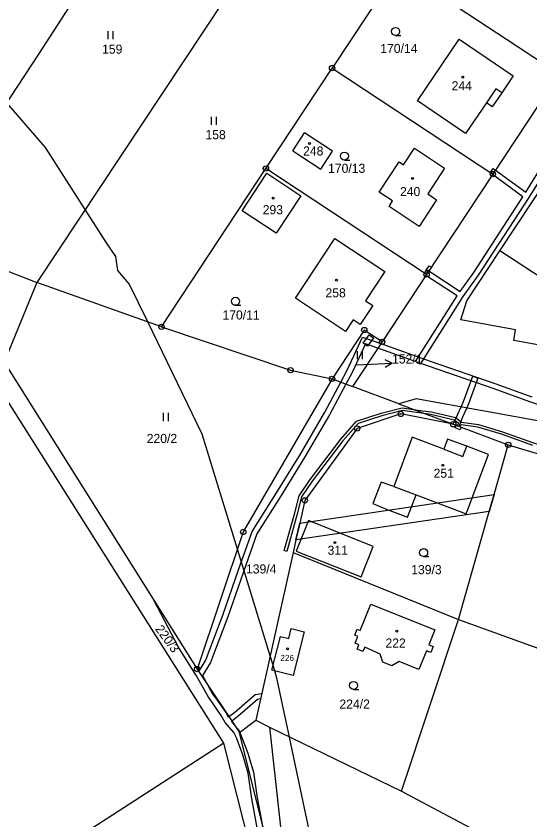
# Model space of a CAD drawing. Extents: x -747333 to -745433, y -1133152 to -1130600.
# Drawn here: x -746635.6 to -746539.4, y -1132011.9 to -1131861.6 of the extents above; entities that cross this region are included whole.
import ezdxf

# ---------------------------------------------------------------- set-up
doc = ezdxf.new("R2010")
doc.units = 0
for name, color, linetype in [('Vrstva 1', 7, 'Continuous'), ('Vrstva 16', 7, 'Continuous'), ('Vrstva 18', 7, 'Continuous'), ('Vrstva 19', 7, 'Continuous'), ('Vrstva 24', 7, 'Continuous'), ('Vrstva 25', 7, 'Continuous'), ('Vrstva 3', 7, 'Continuous'), ('Vrstva 30', 7, 'Continuous'), ('Vrstva 37', 7, 'Continuous'), ('Vrstva 4', 7, 'Continuous'), ('Vrstva 52', 7, 'Continuous'), ('Vrstva 6', 7, 'Continuous')]:
    doc.layers.add(name, color=color, linetype=linetype)

msp = doc.modelspace()

# ---------------------------------------------------------------- linework, layer by layer
at = {"layer": 'Vrstva 1'}
for p, q in [((-746560.48, -1131877.38), (-746552.65, -1131865.89)), ((-746552.65, -1131865.89), (-746542.56, -1131872.76)), ((-746542.56, -1131872.76), (-746544.71, -1131875.9)), ((-746544.71, -1131875.9), (-746546.5, -1131878.51)), ((-746551.46, -1131883.51), (-746560.48, -1131877.38)), ((-746547.57, -1131877.78), (-746551.46, -1131883.51)), ((-746546.5, -1131878.51), (-746547.57, -1131877.78)), ((-746583.8, -1131886.76), (-746581.61, -1131883.41)), ((-746576.33, -1131886.85), (-746581.61, -1131883.41)), ((-746583.8, -1131886.76), (-746578.54, -1131890.2)), ((-746578.54, -1131890.2), (-746576.33, -1131886.85)), ((-746545.06, -1131905.46), (-746534.04, -1131888.76)), ((-746593.25, -1131898.01), (-746588.67, -1131890.97)), ((-746588.67, -1131890.97), (-746582.27, -1131895.15)), ((-746582.27, -1131895.15), (-746586.87, -1131902.18)), ((-746586.87, -1131902.18), (-746593.25, -1131898.01)), ((-746551.21, -1131914.79), (-746545.06, -1131905.46)), ((-746509.16, -1131929.13), (-746545.06, -1131905.46)), ((-746552.36, -1131918.38), (-746551.21, -1131914.79)), ((-746542.1, -1131920.25), (-746552.36, -1131918.38)), ((-746542.46, -1131922.22), (-746542.1, -1131920.25)), ((-746512.94, -1131927.58), (-746542.46, -1131922.22)), ((-746563.94, -1131934.09), (-746572.59, -1131930.85)), ((-746560.7, -1131933.13), (-746563.94, -1131934.09)), ((-746563.94, -1131934.09), (-746559.67, -1131935.69)), ((-746483.07, -1131947.25), (-746560.7, -1131933.13)), ((-746561.44, -1131940.34), (-746564.91, -1131949.57)), ((-746555.51, -1131942.57), (-746561.44, -1131940.34)), ((-746554.83, -1131940.71), (-746555.51, -1131942.57)), ((-746551.26, -1131942.03), (-746554.83, -1131940.71)), ((-746547.16, -1131943.56), (-746551.26, -1131942.03)), ((-746551.34, -1131954.67), (-746547.16, -1131943.56)), ((-746567.28, -1131948.71), (-746568.84, -1131952.76)), ((-746564.91, -1131949.57), (-746567.28, -1131948.71)), ((-746562.32, -1131955.31), (-746560.74, -1131951.14)), ((-746560.74, -1131951.14), (-746551.34, -1131954.67)), ((-746568.84, -1131952.76), (-746566.43, -1131953.71)), ((-746566.43, -1131953.71), (-746562.32, -1131955.31)), ((-746580.87, -1131955.94), (-746583.14, -1131961.66)), ((-746568.74, -1131960.75), (-746580.87, -1131955.94)), ((-746571.01, -1131966.47), (-746568.74, -1131960.75)), ((-746583.14, -1131961.66), (-746571.01, -1131966.47))]:
    msp.add_line(p, q, dxfattribs=at)
for points in [[(-746564.05, -1131852.51), (-746543.81, -1131865.86)], [(-746566.41, -1131856.09), (-746576.43, -1131871.29)], [(-746543.81, -1131865.86), (-746533.99, -1131872.33)], [(-746588.82, -1131890.07), (-746576.43, -1131871.29)], [(-746576.43, -1131871.29), (-746546.37, -1131891.11)], [(-746537.79, -1131878.09), (-746546.37, -1131891.11)], [(-746563.09, -1131889.4), (-746561, -1131886.29)], [(-746561, -1131886.29), (-746555.4, -1131890.01)], [(-746567.62, -1131894.48), (-746563.91, -1131888.85)], [(-746563.91, -1131888.85), (-746563.09, -1131889.4)], [(-746608.35, -1131919.68), (-746588.82, -1131890.07)], [(-746558.76, -1131909.9), (-746588.82, -1131890.07)], [(-746555.4, -1131890.01), (-746558.54, -1131894.79)], [(-746546.37, -1131891.11), (-746558.76, -1131909.9)], [(-746565.11, -1131896.12), (-746567.62, -1131894.48)], [(-746558.54, -1131894.79), (-746556.89, -1131895.9)], [(-746565.79, -1131897.18), (-746565.11, -1131896.12)], [(-746556.89, -1131895.9), (-746560.17, -1131900.92)], [(-746560.17, -1131900.92), (-746565.79, -1131897.18)], [(-746653.72, -1131902.76), (-746631.67, -1131911.42)], [(-746583.31, -1131914.32), (-746575.9, -1131903.14), (-746566.54, -1131909.35), (-746570.17, -1131914.83), (-746568.83, -1131915.71), (-746571.18, -1131919.26), (-746572.49, -1131918.39), (-746573.92, -1131920.55), (-746583.31, -1131914.32)], [(-746558.76, -1131909.9), (-746567.07, -1131922.49)], [(-746631.67, -1131911.42), (-746637.77, -1131926.3)], [(-746608.35, -1131919.68), (-746631.67, -1131911.42)], [(-746608.35, -1131919.68), (-746584.22, -1131927.79)], [(-746570.41, -1131920.29), (-746576.43, -1131929.41)], [(-746567.07, -1131922.49), (-746570.41, -1131920.29)], [(-746637.77, -1131926.3), (-746601.69, -1131983.7)], [(-746584.22, -1131927.79), (-746576.43, -1131929.41)], [(-746576.43, -1131929.41), (-746593.05, -1131958.05)], [(-746576.43, -1131929.41), (-746572.59, -1131930.85)], [(-746596.68, -1131997.54), (-746638.63, -1131931.22)], [(-746559.67, -1131935.69), (-746553.77, -1131937.9)], [(-746563.57, -1131935.97), (-746571.75, -1131938.7)], [(-746553.77, -1131937.9), (-746563.57, -1131935.97)], [(-746553.77, -1131937.9), (-746543.47, -1131941.76)], [(-746571.75, -1131938.7), (-746581.53, -1131952.14)], [(-746546.13, -1131951.07), (-746543.47, -1131941.76)], [(-746543.47, -1131941.76), (-746536.83, -1131943.73)], [(-746581.53, -1131952.14), (-746582.49, -1131956.4)], [(-746547.04, -1131954.23), (-746546.13, -1131951.07)], [(-746552.82, -1131974.44), (-746547.04, -1131954.23)], [(-746582.49, -1131956.4), (-746583.19, -1131959.53)], [(-746593.05, -1131958.05), (-746601.69, -1131983.7)], [(-746583.19, -1131959.53), (-746583.72, -1131961.89)], [(-746583.72, -1131961.89), (-746590.71, -1131993.24)], [(-746583.72, -1131961.89), (-746552.82, -1131974.44)], [(-746571.16, -1131976.49), (-746569.17, -1131971.54)], [(-746569.17, -1131971.54), (-746557.19, -1131976.35)], [(-746563.47, -1132006.55), (-746552.82, -1131974.44)], [(-746552.82, -1131974.44), (-746522.94, -1131985.19)], [(-746584.55, -1131977.99), (-746584.07, -1131976.1)], [(-746584.07, -1131976.1), (-746581.67, -1131976.71)], [(-746572.17, -1131977.38), (-746571.72, -1131976.26)], [(-746571.72, -1131976.26), (-746571.16, -1131976.49)], [(-746587.73, -1131983.9), (-746586.1, -1131977.6)], [(-746586.1, -1131977.6), (-746584.55, -1131977.99)], [(-746581.67, -1131976.71), (-746583.74, -1131984.9)], [(-746571.61, -1131977.61), (-746572.17, -1131977.38)], [(-746572.11, -1131978.85), (-746571.61, -1131977.61)], [(-746557.19, -1131976.35), (-746558.32, -1131979.15)], [(-746571.41, -1131979.15), (-746572.11, -1131978.85)], [(-746571.75, -1131979.95), (-746571.41, -1131979.15)], [(-746558.32, -1131979.15), (-746557.5, -1131979.48)], [(-746570.68, -1131980.42), (-746571.75, -1131979.95)], [(-746570.33, -1131979.62), (-746570.68, -1131980.42)], [(-746567.42, -1131980.89), (-746570.33, -1131979.62)], [(-746558.77, -1131980.29), (-746560.18, -1131983.8)], [(-746557.96, -1131980.63), (-746558.77, -1131980.29)], [(-746557.5, -1131979.48), (-746557.96, -1131980.63)], [(-746566.96, -1131982.4), (-746567.42, -1131980.89)], [(-746563.92, -1131982.3), (-746565.28, -1131983.08)], [(-746560.18, -1131983.8), (-746563.92, -1131982.3)], [(-746601.69, -1131983.7), (-746593.75, -1131995.59)], [(-746565.28, -1131983.08), (-746566.96, -1131982.4)], [(-746583.74, -1131984.9), (-746587.73, -1131983.9)], [(-746593.75, -1131995.59), (-746590.71, -1131993.24)], [(-746590.71, -1131993.24), (-746588.16, -1131994.6)], [(-746587.02, -1132022.55), (-746593.75, -1131995.59)], [(-746588.16, -1131994.6), (-746583.35, -1132038.1)], [(-746588.16, -1131994.6), (-746563.47, -1132006.55)], [(-746596.68, -1131997.54), (-746655.89, -1132035.79)], [(-746590.52, -1132021.94), (-746596.68, -1131997.54)], [(-746563.47, -1132006.55), (-746549.71, -1132013.83)]]:
    msp.add_lwpolyline(points, dxfattribs=at)
at = {"layer": 'Vrstva 16'}
msp.add_line((-746566.554393, -1131925.815687), (-746565.22363, -1131926.509639), dxfattribs=at)
for points in [[(-746569.22, -1131926.68), (-746565.22363, -1131926.509639), (-746566.490507, -1131927.314326)], [(-746571.85, -1131926.79), (-746569.22, -1131926.68)]]:
    msp.add_lwpolyline(points, dxfattribs=at)
at = {"layer": 'Vrstva 24'}
for p, q in [((-746576.48, -1131871.29), (-746576.38, -1131871.29)), ((-746588.87, -1131890.07), (-746588.77, -1131890.07)), ((-746546.42, -1131891.11), (-746546.32, -1131891.11)), ((-746558.81, -1131909.9), (-746558.71, -1131909.9)), ((-746608.4, -1131919.68), (-746608.3, -1131919.68)), ((-746570.46, -1131920.29), (-746570.36, -1131920.29)), ((-746567.12, -1131922.49), (-746567.02, -1131922.49)), ((-746584.27, -1131927.79), (-746584.17, -1131927.79)), ((-746576.48, -1131929.41), (-746576.38, -1131929.41)), ((-746563.62, -1131935.97), (-746563.52, -1131935.97)), ((-746553.82, -1131937.9), (-746553.72, -1131937.9)), ((-746571.8, -1131938.7), (-746571.7, -1131938.7)), ((-746543.52, -1131941.76), (-746543.42, -1131941.76)), ((-746581.58, -1131952.14), (-746581.48, -1131952.14)), ((-746593.1, -1131958.05), (-746593, -1131958.05)), ((-746601.74, -1131983.7), (-746601.64, -1131983.7))]:
    msp.add_line(p, q, dxfattribs=at)
for centre in [(-746576.43, -1131871.29), (-746588.82, -1131890.07), (-746546.37, -1131891.11), (-746558.76, -1131909.9), (-746608.35, -1131919.68), (-746570.41, -1131920.29), (-746567.07, -1131922.49), (-746584.22, -1131927.79), (-746576.43, -1131929.41), (-746563.57, -1131935.97), (-746571.75, -1131938.7), (-746553.77, -1131937.9), (-746543.47, -1131941.76), (-746581.53, -1131952.14), (-746593.05, -1131958.05), (-746601.69, -1131983.7)]:
    msp.add_circle(centre, 0.499289, dxfattribs=at)
at = {"layer": 'Vrstva 25'}
for p, q in [((-746618.4, -1131864.39), (-746618.4, -1131865.89)), ((-746617.4, -1131865.89), (-746617.4, -1131864.39)), ((-746564.55, -1131865.19), (-746563.55, -1131865.19)), ((-746599.04, -1131880.39), (-746599.04, -1131881.89)), ((-746598.04, -1131881.89), (-746598.04, -1131880.39)), ((-746574.13, -1131888.49), (-746573.13, -1131888.49)), ((-746594.5, -1131915.66), (-746593.5, -1131915.66)), ((-746571.76, -1131924.21), (-746571.76, -1131925.71)), ((-746570.76, -1131925.71), (-746570.76, -1131924.21)), ((-746608.03, -1131935.8), (-746608.03, -1131937.3)), ((-746607.03, -1131937.3), (-746607.03, -1131935.8)), ((-746559.31, -1131962.67), (-746558.31, -1131962.67)), ((-746572.41, -1131987.51), (-746571.41, -1131987.51))]:
    msp.add_line(p, q, dxfattribs=at)
for centre, radius in [((-746564.55, -1131864.44), 0.75), ((-746552, -1131872.99), 0.174503), ((-746580.65, -1131885.39), 0.174503), ((-746574.13, -1131887.74), 0.75), ((-746561.39, -1131891.91), 0.174503), ((-746587.44, -1131895.62), 0.174503), ((-746575.62, -1131910.97), 0.174503), ((-746594.5, -1131914.91), 0.75), ((-746555.71, -1131945.59), 0.174503), ((-746575.9, -1131960.05), 0.174503), ((-746559.31, -1131961.92), 0.75), ((-746564.32, -1131976.6), 0.174503), ((-746584.75, -1131979.9), 0.174503), ((-746572.41, -1131986.76), 0.75)]:
    msp.add_circle(centre, radius, dxfattribs=at)
at = {"layer": 'Vrstva 3'}
for points in [[(-746560.48, -1131877.38), (-746552.65, -1131865.89)], [(-746552.65, -1131865.89), (-746542.56, -1131872.76)], [(-746542.56, -1131872.76), (-746544.71, -1131875.9)], [(-746545.8, -1131875.16), (-746547.57, -1131877.78)], [(-746544.71, -1131875.9), (-746545.8, -1131875.16)], [(-746551.46, -1131883.51), (-746560.48, -1131877.38)], [(-746547.57, -1131877.78), (-746551.46, -1131883.51)], [(-746583.8, -1131886.76), (-746581.61, -1131883.41)], [(-746576.33, -1131886.85), (-746581.61, -1131883.41)], [(-746583.8, -1131886.76), (-746578.54, -1131890.2)], [(-746578.54, -1131890.2), (-746576.33, -1131886.85)], [(-746563.09, -1131889.4), (-746561, -1131886.29)], [(-746561, -1131886.29), (-746555.4, -1131890.01)], [(-746567.62, -1131894.48), (-746563.91, -1131888.85)], [(-746563.91, -1131888.85), (-746563.09, -1131889.4)], [(-746555.4, -1131890.01), (-746558.54, -1131894.79)], [(-746593.25, -1131898.01), (-746588.67, -1131890.97)], [(-746588.67, -1131890.97), (-746582.27, -1131895.15)], [(-746565.11, -1131896.12), (-746567.62, -1131894.48)], [(-746558.54, -1131894.79), (-746556.89, -1131895.9)], [(-746582.27, -1131895.15), (-746586.87, -1131902.18)], [(-746565.79, -1131897.18), (-746565.11, -1131896.12)], [(-746556.89, -1131895.9), (-746560.17, -1131900.92)], [(-746586.87, -1131902.18), (-746593.25, -1131898.01)], [(-746560.17, -1131900.92), (-746565.79, -1131897.18)], [(-746583.31, -1131914.32), (-746575.9, -1131903.14), (-746566.54, -1131909.35), (-746570.17, -1131914.83), (-746568.83, -1131915.71), (-746571.18, -1131919.26), (-746572.49, -1131918.39), (-746573.92, -1131920.55), (-746583.31, -1131914.32)], [(-746561.44, -1131940.34), (-746564.91, -1131949.57)], [(-746555.51, -1131942.57), (-746561.44, -1131940.34)], [(-746555.51, -1131942.57), (-746551.96, -1131943.91)], [(-746551.96, -1131943.91), (-746551.26, -1131942.03)], [(-746547.16, -1131943.56), (-746551.26, -1131942.03)], [(-746551.34, -1131954.67), (-746547.16, -1131943.56)], [(-746564.91, -1131949.57), (-746560.74, -1131951.14)], [(-746560.74, -1131951.14), (-746551.34, -1131954.67)], [(-746580.87, -1131955.94), (-746583.14, -1131961.66)], [(-746568.74, -1131960.75), (-746580.87, -1131955.94)], [(-746571.01, -1131966.47), (-746568.74, -1131960.75)], [(-746583.14, -1131961.66), (-746571.01, -1131966.47)], [(-746571.16, -1131976.49), (-746569.17, -1131971.54)], [(-746569.17, -1131971.54), (-746557.19, -1131976.35)], [(-746584.55, -1131977.99), (-746584.07, -1131976.1)], [(-746584.07, -1131976.1), (-746581.67, -1131976.71)], [(-746572.17, -1131977.38), (-746571.72, -1131976.26)], [(-746571.72, -1131976.26), (-746571.16, -1131976.49)], [(-746587.73, -1131983.9), (-746586.1, -1131977.6)], [(-746586.1, -1131977.6), (-746584.55, -1131977.99)], [(-746581.67, -1131976.71), (-746583.74, -1131984.9)], [(-746571.61, -1131977.61), (-746572.17, -1131977.38)], [(-746572.11, -1131978.85), (-746571.61, -1131977.61)], [(-746557.19, -1131976.35), (-746558.32, -1131979.15)], [(-746571.41, -1131979.15), (-746572.11, -1131978.85)], [(-746571.75, -1131979.95), (-746571.41, -1131979.15)], [(-746558.32, -1131979.15), (-746557.5, -1131979.48)], [(-746570.68, -1131980.42), (-746571.75, -1131979.95)], [(-746570.33, -1131979.62), (-746570.68, -1131980.42)], [(-746567.42, -1131980.89), (-746570.33, -1131979.62)], [(-746558.77, -1131980.29), (-746560.18, -1131983.8)], [(-746557.96, -1131980.63), (-746558.77, -1131980.29)], [(-746557.5, -1131979.48), (-746557.96, -1131980.63)], [(-746566.96, -1131982.4), (-746567.42, -1131980.89)], [(-746563.92, -1131982.3), (-746565.28, -1131983.08)], [(-746560.18, -1131983.8), (-746563.92, -1131982.3)], [(-746565.28, -1131983.08), (-746566.96, -1131982.4)], [(-746583.74, -1131984.9), (-746587.73, -1131983.9)]]:
    msp.add_lwpolyline(points, dxfattribs=at)
at = {"layer": 'Vrstva 30'}
for p, q in [((-746540.19, -1131894.51), (-746536.61, -1131888.75)), ((-746546.79, -1131890.84), (-746546.28, -1131890.07)), ((-746546.28, -1131890.07), (-746545.88, -1131890.36)), ((-746545.88, -1131890.36), (-746540.19, -1131894.51)), ((-746536.02, -1131889.7), (-746539.63, -1131895.5)), ((-746546.37, -1131891.11), (-746546.79, -1131890.84)), ((-746546.43, -1131891.2), (-746546.37, -1131891.11)), ((-746540.73, -1131895.35), (-746546.43, -1131891.2)), ((-746549.92, -1131909.49), (-746540.73, -1131895.35)), ((-746539.63, -1131895.5), (-746549.1, -1131910.05)), ((-746558.82, -1131909.09), (-746558.27, -1131908.25)), ((-746558.27, -1131908.25), (-746557.86, -1131908.53)), ((-746557.86, -1131908.53), (-746557.99, -1131908.74)), ((-746559.18, -1131909.62), (-746558.74, -1131908.96)), ((-746558.76, -1131909.9), (-746559.18, -1131909.62)), ((-746558.87, -1131910.07), (-746558.76, -1131909.9)), ((-746553.06, -1131913.88), (-746558.87, -1131910.07)), ((-746558.41, -1131909.37), (-746558.82, -1131909.09)), ((-746558.74, -1131908.96), (-746558.32, -1131909.23)), ((-746558.27, -1131909.16), (-746558.41, -1131909.37)), ((-746558.32, -1131909.23), (-746552.5, -1131913.05)), ((-746557.99, -1131908.74), (-746558.27, -1131909.16)), ((-746552.5, -1131913.05), (-746549.92, -1131909.49)), ((-746549.1, -1131910.05), (-746551.96, -1131914.01)), ((-746560.83, -1131926.14), (-746553.06, -1131913.88)), ((-746551.96, -1131914.01), (-746559.99, -1131926.68)), ((-746570.62, -1131922.75), (-746569.5, -1131921.16)), ((-746568.68, -1131921.74), (-746569.8, -1131923.33)), ((-746569.5, -1131921.16), (-746568.68, -1131921.74)), ((-746569.8, -1131923.33), (-746570.62, -1131922.75)), ((-746559.99, -1131926.68), (-746560.83, -1131926.14)), ((-746551.86, -1131933.68), (-746550.13, -1131928.92)), ((-746549.15, -1131929.28), (-746550.9, -1131934.08)), ((-746550.13, -1131928.92), (-746549.15, -1131929.28)), ((-746552.31, -1131934.66), (-746551.86, -1131933.68)), ((-746550.9, -1131934.08), (-746551.25, -1131934.85)), ((-746553, -1131936.16), (-746552.31, -1131934.66)), ((-746551.25, -1131934.85), (-746552.04, -1131936.56)), ((-746553.77, -1131937.9), (-746553, -1131936.16)), ((-746552.04, -1131936.56), (-746552.7, -1131938.3)), ((-746552.7, -1131938.3), (-746553.77, -1131937.9))]:
    msp.add_line(p, q, dxfattribs=at)
for points in [[(-746546.37, -1131891.11), (-746545.88, -1131890.36)], [(-746545.88, -1131890.36), (-746546.37, -1131891.11)], [(-746558.32, -1131909.23), (-746558.76, -1131909.9)], [(-746558.76, -1131909.9), (-746558.32, -1131909.23)], [(-746573.6, -1131927.8), (-746570.73, -1131921.61)], [(-746570.73, -1131921.61), (-746567.3, -1131922.83)], [(-746570.21, -1131922.86), (-746572.7, -1131928.24)], [(-746567.86, -1131923.69), (-746570.21, -1131922.86)], [(-746567.3, -1131922.83), (-746558.1, -1131926.1)], [(-746558.42, -1131927.04), (-746567.86, -1131923.69)], [(-746558.1, -1131926.1), (-746545.8, -1131930.35)], [(-746574.79, -1131930.03), (-746573.6, -1131927.8)], [(-746546.14, -1131931.29), (-746558.42, -1131927.04)], [(-746572.7, -1131928.24), (-746573.84, -1131930.38)], [(-746577.79, -1131935.64), (-746574.79, -1131930.03)], [(-746573.84, -1131930.38), (-746576.91, -1131936.13)], [(-746545.8, -1131930.35), (-746539.1, -1131932.8)], [(-746539.44, -1131933.74), (-746546.14, -1131931.29)], [(-746526.93, -1131937.92), (-746539.44, -1131933.74)], [(-746582.37, -1131943.48), (-746577.79, -1131935.64)], [(-746567.27, -1131935.86), (-746563.3, -1131934.84), (-746559.47, -1131935.38), (-746557.85, -1131935.61), (-746553.37, -1131936.66)], [(-746553.59, -1131937.12), (-746557.95, -1131936.11), (-746563.28, -1131935.34), (-746567.13, -1131936.34)], [(-746576.91, -1131936.13), (-746581.51, -1131944)], [(-746580.54, -1131948.27), (-746574.83, -1131940.68), (-746571.84, -1131937.3), (-746567.27, -1131935.86)], [(-746567.13, -1131936.34), (-746571.56, -1131937.74), (-746574.45, -1131941)], [(-746538.91, -1131941.89), (-746544.74, -1131939.78), (-746549.15, -1131938.47), (-746552.27, -1131938.03), (-746552.58, -1131938.35), (-746553.1, -1131938.15), (-746552.74, -1131937.79), (-746553.59, -1131937.12)], [(-746553.37, -1131936.66), (-746552.26, -1131937.53), (-746549.05, -1131937.97), (-746544.58, -1131939.3)], [(-746553.22, -1131938.11), (-746553.1, -1131938.15), (-746552.58, -1131938.35), (-746552.28, -1131938.46), (-746552.46, -1131938.93), (-746553.4, -1131938.57), (-746553.22, -1131938.11)], [(-746544.58, -1131939.3), (-746538.75, -1131941.41), (-746535.87, -1131942.28)], [(-746574.45, -1131941), (-746580.14, -1131948.57), (-746582.14, -1131951.51)], [(-746586.84, -1131950.74), (-746582.37, -1131943.48)], [(-746581.51, -1131944), (-746585.98, -1131951.26)], [(-746583.49, -1131954.75), (-746582.6, -1131951.31), (-746580.54, -1131948.27)], [(-746591.4, -1131957.96), (-746586.84, -1131950.74)], [(-746585.98, -1131951.26), (-746590.5, -1131958.4)], [(-746582.14, -1131951.51), (-746583.01, -1131954.89), (-746584.92, -1131961.68), (-746585.4, -1131961.54)], [(-746582.49, -1131956.4), (-746546.13, -1131951.07), (-746547.04, -1131954.23), (-746583.19, -1131959.53), (-746582.49, -1131956.4)], [(-746585.4, -1131961.54), (-746583.49, -1131954.75)], [(-746593.95, -1131965.17), (-746591.4, -1131957.96)], [(-746590.5, -1131958.4), (-746593.01, -1131965.51)], [(-746596.88, -1131973.6), (-746593.95, -1131965.17)], [(-746593.01, -1131965.51), (-746595.94, -1131973.94)], [(-746609.78, -1131970.82), (-746601.69, -1131983.7)], [(-746605.13, -1131979.72), (-746609.78, -1131970.82)], [(-746599.53, -1131980.64), (-746596.88, -1131973.6)], [(-746595.94, -1131973.94), (-746598.59, -1131981)], [(-746601.78, -1131984.96), (-746605.13, -1131979.72)], [(-746600.06, -1131982.03), (-746599.53, -1131980.64)], [(-746601.25, -1131983.94), (-746600.06, -1131982.03)], [(-746598.59, -1131981), (-746599.16, -1131982.49)], [(-746601.69, -1131983.7), (-746601.59, -1131983.41)], [(-746601.59, -1131983.41), (-746601.25, -1131983.94)], [(-746599.16, -1131982.49), (-746600.67, -1131984.9)], [(-746599.58, -1131988.97), (-746601.78, -1131984.96)], [(-746600.67, -1131984.9), (-746599.68, -1131986.71)], [(-746599.68, -1131986.71), (-746598.74, -1131988.43)], [(-746590.84, -1131988.43), (-746589.6, -1131988.25)], [(-746589.6, -1131988.25), (-746589.83, -1131989.29)], [(-746599.08, -1131989.67), (-746599.58, -1131988.97)], [(-746597.18, -1131992.39), (-746599.08, -1131989.67)], [(-746598.74, -1131988.43), (-746598.26, -1131989.09)], [(-746598.26, -1131989.09), (-746596.34, -1131991.85)], [(-746594.67, -1131991.81), (-746590.84, -1131988.43)], [(-746590.4, -1131989.37), (-746594.04, -1131992.59)], [(-746589.83, -1131989.29), (-746590.4, -1131989.37)], [(-746596.42, -1131993.71), (-746597.18, -1131992.39)], [(-746596.34, -1131991.85), (-746595.86, -1131992.69)], [(-746595.86, -1131992.69), (-746595.75, -1131992.6)], [(-746595.75, -1131992.6), (-746594.67, -1131991.81)], [(-746594.04, -1131992.59), (-746595.19, -1131993.43)], [(-746594.79, -1131995.56), (-746596.42, -1131993.71)], [(-746595.19, -1131993.43), (-746595.28, -1131993.5)], [(-746595.28, -1131993.5), (-746594.74, -1131994.11)], [(-746594.74, -1131994.11), (-746593.93, -1131995.02)], [(-746594.34, -1131996.59), (-746594.79, -1131995.56)], [(-746593.93, -1131995.02), (-746593.7, -1131995.55)], [(-746593.7, -1131995.55), (-746593.42, -1131996.21)], [(-746593.13, -1131999.74), (-746594.34, -1131996.59)], [(-746593.42, -1131996.21), (-746592.18, -1131999.42)], [(-746592.12, -1132003.16), (-746593.13, -1131999.74)], [(-746592.18, -1131999.42), (-746591.14, -1132002.96)], [(-746591.44, -1132007.92), (-746592.12, -1132003.16)], [(-746591.14, -1132002.96), (-746590.46, -1132007.76)], [(-746590.46, -1132007.76), (-746589.73, -1132011.7)], [(-746589.93, -1132016.14), (-746591.44, -1132007.92)], [(-746589.73, -1132011.7), (-746588.93, -1132016)]]:
    msp.add_lwpolyline(points, dxfattribs=at)
at = {"layer": 'Vrstva 37'}
for centre in [(-746552, -1131872.99), (-746580.65, -1131885.39), (-746561.39, -1131891.91), (-746587.44, -1131895.62), (-746575.62, -1131910.97), (-746555.71, -1131945.59), (-746575.9, -1131960.05), (-746564.32, -1131976.6), (-746584.75, -1131979.9)]:
    msp.add_circle(centre, 0.174503, dxfattribs=at)
at = {"layer": 'Vrstva 4'}
for p, q in [((-746545.8, -1131875.16), (-746547.57, -1131877.78)), ((-746544.71, -1131875.9), (-746545.8, -1131875.16)), ((-746555.51, -1131942.57), (-746551.96, -1131943.91)), ((-746551.96, -1131943.91), (-746551.26, -1131942.03)), ((-746564.91, -1131949.57), (-746560.74, -1131951.14))]:
    msp.add_line(p, q, dxfattribs=at)
at = {"layer": 'Vrstva 52'}
msp.add_lwpolyline([(-746571.81, -1132033.63), (-746576.94, -1132026), (-746580.31, -1132015.87), (-746583.66, -1132000), (-746584.41, -1131996.41), (-746586.69, -1131985.63), (-746587.17, -1131984.04), (-746587.49, -1131982.99), (-746588.03, -1131981.23), (-746594.14, -1131961.3), (-746600.75, -1131939.75), (-746610.91, -1131918.77), (-746614.38, -1131911.62), (-746616.5, -1131909.13), (-746616.87, -1131906.5), (-746618.63, -1131904), (-746622.62, -1131897.75), (-746630.06, -1131886.12), (-746637.28, -1131877.8)], dxfattribs=at)
at = {"layer": 'Vrstva 6'}
for points in [[(-746631.27, -1131868.67), (-746609.27, -1131834.66)], [(-746588.71, -1131846.53), (-746631.67, -1131911.42)], [(-746653.72, -1131902.76), (-746631.27, -1131868.67)], [(-746567.07, -1131922.49), (-746572.59, -1131930.85)]]:
    msp.add_lwpolyline(points, dxfattribs=at)

# ---------------------------------------------------------------- texts
at = {"layer": 'Vrstva 16'}
msp.add_text('152/1', height=1.7, dxfattribs=at).set_placement((-746565.22, -1131926.55))
at = {"layer": 'Vrstva 18'}
for s, p in [('159', (-746619.46, -1131868.59)), ('170/14', (-746567.415458, -1131868.46)), ('158', (-746600.12, -1131884.59)), ('170/13', (-746577.185458, -1131890.88)), ('170/11', (-746596.942722, -1131918.32)), ('220/2', (-746611.11, -1131941.41)), ('139/4', (-746592.54, -1131965.82)), ('139/3', (-746561.63, -1131965.95)), ('224/2', (-746575.06, -1131991.1))]:
    msp.add_text(s, height=1.7, dxfattribs=at).set_placement(p)
for s, height, rotation, p in [('152/1', 0.1, 58.80168, (-746571.85, -1131926.79)), ('220/3', 1.7, 306.44946, (-746609.62, -1131976.23))]:
    msp.add_text(s, height=height, rotation=rotation, dxfattribs=at).set_placement(p)
at = {"layer": 'Vrstva 19'}
for s, height, p in [('244', 1.7, (-746554.071545, -1131875.44)), ('248', 1.7, (-746581.851545, -1131887.64)), ('240', 1.7, (-746563.726548, -1131895.23)), ('293', 1.7, (-746589.417405, -1131898.63)), ('258', 1.7, (-746577.671545, -1131914.17)), ('251', 1.7, (-746557.44881, -1131947.91)), ('311', 1.7, (-746577.276074, -1131962.32)), ('222', 1.7, (-746566.45, -1131979.68)), ('226', 1.14, (-746586.11, -1131982.19))]:
    msp.add_text(s, height=height, dxfattribs=at).set_placement(p)

doc.saveas('drawing.dxf')
